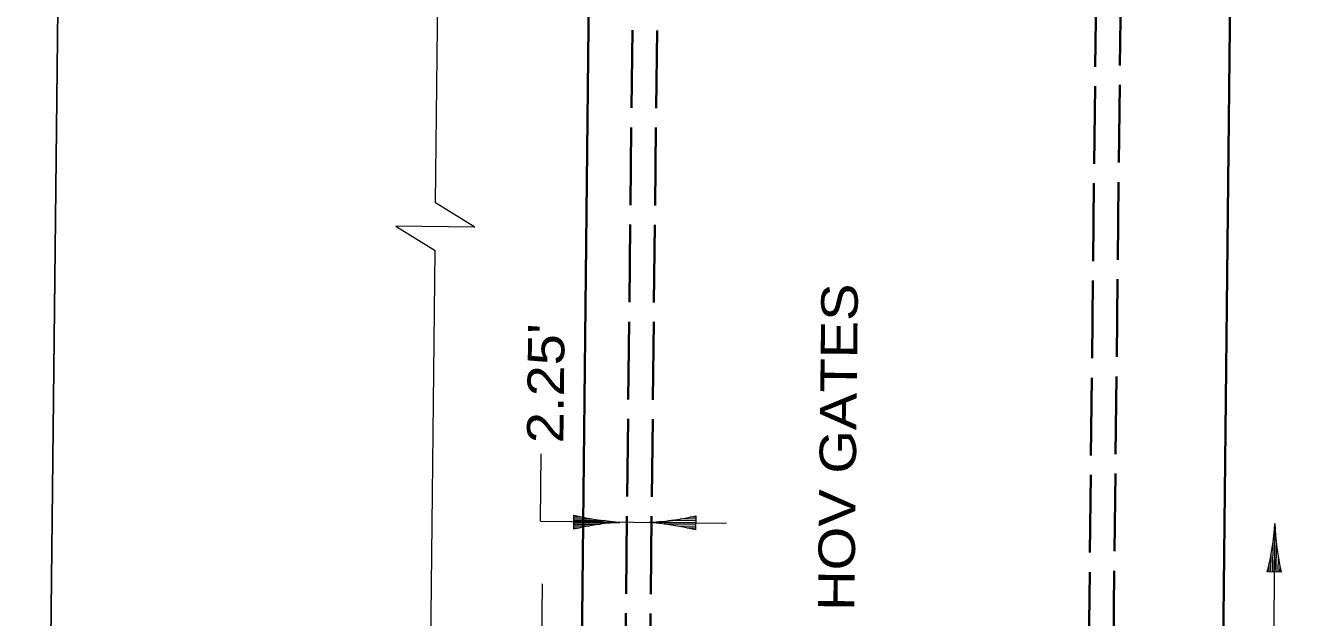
# Model space of a CAD drawing. Extents: x 2356576 to 2377878, y 6966390 to 6990634.
# Drawn here: x 2366091 to 2366792, y 6974891 to 6975215 of the extents above; entities that cross this region are included whole.
import ezdxf

# ---------------------------------------------------------------- set-up
doc = ezdxf.new("R2010")
doc.units = 0
doc.header["$LTSCALE"] = 7.1
doc.linetypes.add('LONG_DASHED', pattern=[7.5, 6, -1.5])
doc.layers.add('19', color=7, linetype='Continuous', lineweight=13)
doc.layers.add('8', color=7, linetype='Continuous', lineweight=13)

msp = doc.modelspace()

# ---------------------------------------------------------------- linework, layer by layer
at = {"layer": '19'}
for p, q in [((2366316.114, 6975117.774), (2366322.458, 6975689.086)), ((2366337.594, 6975104.466), (2366316.114, 6975117.774)), ((2366310.202, 6974585.516), (2366315.824, 6975091.638)), ((2366373.522, 6974943.276), (2366373.932, 6974980.13)), ((2366391.866, 6974945.646), (2366396.628, 6974945.646)), ((2366391.87, 6974938.944), (2366391.868, 6974946.606)), ((2366391.868, 6974944.646), (2366401.592, 6974944.646)), ((2366391.868, 6974943.646), (2366409.088, 6974943.644)), ((2366458.624, 6974943.434), (2366443.928, 6974943.612)), ((2366458.638, 6974944.434), (2366450.088, 6974944.54)), ((2366458.648, 6974945.434), (2366455.48, 6974945.474)), ((2366458.658, 6974946.136), (2366458.564, 6974938.476)), ((2366373.522, 6974943.276), (2366475.56, 6974942.142)), ((2366391.866, 6974942.648), (2366416.994, 6974942.648)), ((2366391.866, 6974940.646), (2366400.422, 6974940.644)), ((2366391.87, 6974939.646), (2366395.038, 6974939.648)), ((2366391.872, 6974941.646), (2366406.566, 6974941.646)), ((2366458.612, 6974942.434), (2366433.488, 6974942.738)), ((2366458.602, 6974941.436), (2366441.382, 6974941.646)), ((2366458.588, 6974940.434), (2366448.868, 6974940.552)), ((2366458.58, 6974939.434), (2366453.818, 6974939.492)), ((2366776.044, 6974941.752), (2366774.882, 6974837.368)), ((2366775.854, 6974915.446), (2366776.156, 6974940.57)), ((2366774.856, 6974915.458), (2366775.066, 6974932.676)), ((2366776.854, 6974915.436), (2366777.03, 6974930.13)), ((2366773.854, 6974915.47), (2366773.972, 6974925.192)), ((2366777.854, 6974915.42), (2366777.958, 6974923.972)), ((2366772.854, 6974915.48), (2366772.91, 6974920.242)), ((2366778.854, 6974915.41), (2366778.892, 6974918.578)), ((2366373.51, 6974804.558), (2366374.668, 6974908.942)), ((2366779.556, 6974915.402), (2366771.894, 6974915.494))]:
    msp.add_line(p, q, dxfattribs=at)
at = {"layer": '19', "lineweight": 35}
for p, q in [((2366392.98, 6974584.292), (2366405.238, 6975688.026)), ((2366737.734, 6973980.518), (2366756.652, 6975684.12))]:
    msp.add_line(p, q, dxfattribs=at)
at = {"layer": '19', "linetype": 'LONG_DASHED', "lineweight": 35}
for p, q in [((2366416.98, 6974584.026), (2366429.232, 6975687.326)), ((2366430.48, 6974583.876), (2366442.728, 6975686.9)), ((2366670.546, 6974553.35), (2366683.116, 6975684.936)), ((2366684.054, 6974554.04), (2366696.614, 6975684.786))]:
    msp.add_line(p, q, dxfattribs=at)
at = {"layer": '19', "lineweight": 25}
msp.add_lwpolyline([(2366974.866, 6973617.03), (2367000.838, 6975955.59), (2366117.376, 6975965.402), (2366091.406, 6973626.842)], close=True, dxfattribs=at)
at = {"layer": '19'}
msp.add_lwpolyline([(2366337.592, 6975104.466), (2366294.342, 6975104.946), (2366315.824, 6975091.638)], dxfattribs=at)
for centre, start, end in [((2366425.651, 6975087.024), 256.47239, 267.15844), ((2366426.573, 6975086.95), 272.14997, 282.83602), ((2366425.661, 6974798.53), 92.84556, 103.53161), ((2366423.081, 6974798.477), 75.77681, 86.46286), ((2366631.896, 6974950.978), 345.77681, 356.46286), ((2366920.369, 6974947.486), 182.14997, 192.83602)]:
    msp.add_arc(centre, 144.425, start, end, dxfattribs=at)
at = {"layer": '8'}
for p, q in [((2366316.114, 6975117.774), (2366322.458, 6975689.086)), ((2366337.594, 6975104.466), (2366316.114, 6975117.774)), ((2366310.202, 6974585.516), (2366315.824, 6975091.638)), ((2366373.522, 6974943.276), (2366373.932, 6974980.13)), ((2366391.866, 6974945.646), (2366396.628, 6974945.646)), ((2366391.87, 6974938.944), (2366391.868, 6974946.606)), ((2366391.868, 6974944.646), (2366401.592, 6974944.646)), ((2366391.868, 6974943.646), (2366409.088, 6974943.644)), ((2366458.624, 6974943.434), (2366443.928, 6974943.612)), ((2366458.638, 6974944.434), (2366450.088, 6974944.54)), ((2366458.648, 6974945.434), (2366455.48, 6974945.474)), ((2366458.658, 6974946.136), (2366458.564, 6974938.476)), ((2366373.522, 6974943.276), (2366475.56, 6974942.142)), ((2366391.866, 6974942.648), (2366416.994, 6974942.648)), ((2366391.866, 6974940.646), (2366400.422, 6974940.644)), ((2366391.87, 6974939.646), (2366395.038, 6974939.648)), ((2366391.872, 6974941.646), (2366406.566, 6974941.646)), ((2366458.612, 6974942.434), (2366433.488, 6974942.738)), ((2366458.602, 6974941.436), (2366441.382, 6974941.646)), ((2366458.588, 6974940.434), (2366448.868, 6974940.552)), ((2366458.58, 6974939.434), (2366453.818, 6974939.492)), ((2366776.044, 6974941.752), (2366774.882, 6974837.368)), ((2366775.854, 6974915.446), (2366776.156, 6974940.57)), ((2366774.856, 6974915.458), (2366775.066, 6974932.676)), ((2366776.854, 6974915.436), (2366777.03, 6974930.13)), ((2366773.854, 6974915.47), (2366773.972, 6974925.192)), ((2366777.854, 6974915.42), (2366777.958, 6974923.972)), ((2366772.854, 6974915.48), (2366772.91, 6974920.242)), ((2366778.854, 6974915.41), (2366778.892, 6974918.578)), ((2366373.51, 6974804.558), (2366374.668, 6974908.942)), ((2366779.556, 6974915.402), (2366771.894, 6974915.494))]:
    msp.add_line(p, q, dxfattribs=at)
at = {"layer": '8', "lineweight": 35}
for p, q in [((2366392.98, 6974584.292), (2366405.238, 6975688.026)), ((2366737.734, 6973980.518), (2366756.652, 6975684.12))]:
    msp.add_line(p, q, dxfattribs=at)
at = {"layer": '8', "linetype": 'LONG_DASHED', "lineweight": 35}
for p, q in [((2366416.98, 6974584.026), (2366429.232, 6975687.326)), ((2366430.48, 6974583.876), (2366442.728, 6975686.9)), ((2366670.546, 6974553.35), (2366683.116, 6975684.936)), ((2366684.054, 6974554.04), (2366696.614, 6975684.786))]:
    msp.add_line(p, q, dxfattribs=at)
at = {"layer": '8', "lineweight": 25}
msp.add_lwpolyline([(2366974.866, 6973617.03), (2367000.838, 6975955.59), (2366117.376, 6975965.402), (2366091.406, 6973626.842)], close=True, dxfattribs=at)
at = {"layer": '8'}
msp.add_lwpolyline([(2366337.592, 6975104.466), (2366294.342, 6975104.946), (2366315.824, 6975091.638)], dxfattribs=at)
for centre, start, end in [((2366425.651, 6975087.024), 256.47239, 267.15844), ((2366426.573, 6975086.95), 272.14997, 282.83602), ((2366425.661, 6974798.53), 92.84556, 103.53161), ((2366423.081, 6974798.477), 75.77681, 86.46286), ((2366631.896, 6974950.978), 345.77681, 356.46286), ((2366920.369, 6974947.486), 182.14997, 192.83602)]:
    msp.add_arc(centre, 144.425, start, end, dxfattribs=at)

# ---------------------------------------------------------------- texts
at = {"layer": '19', "width": 1.15}
for s, p in [('HOV GATES', (2366545.596, 6974894.004)), ("2.25'", (2366386.126, 6974985.864))]:
    msp.add_text(s, height=20, rotation=89.364, dxfattribs=at).set_placement(p)
at = {"layer": '8', "width": 1.15}
for s, p in [('HOV GATES', (2366545.596, 6974894.004)), ("2.25'", (2366386.126, 6974985.864))]:
    msp.add_text(s, height=20, rotation=89.364, dxfattribs=at).set_placement(p)

doc.saveas('drawing.dxf')
